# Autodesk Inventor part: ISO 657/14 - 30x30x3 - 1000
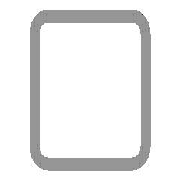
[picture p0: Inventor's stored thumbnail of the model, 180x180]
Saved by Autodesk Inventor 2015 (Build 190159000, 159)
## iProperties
Created: 2014-02
Part Number: ISO 657/14 - 30x30x3 - 1000
Material: Steel, Mild
Description: Hot-rolled steel sections - part 14: hot-finished structrual hollow sections - Dimensions and sectional properties
Document SubType Name: Modeling
Standard: ISO
Designer: 徐冠倫
Standard Revision: Third edition 2000-03-15
Standards Organization: ISO
Language: en-US
Size Designation: 30x30x3
Categories: <MemberInstance><Categories><Category DisplayName="Structural Shapes" InternalName="089c4875-fa83-4c05-b084-43b9cc11f5ed" Mnemonic="GRDR"><CategoryParameter Dis
Stock Number: 30x30x3
Mass: 2422.11 g
Surface Area: 2063.16 cm^2
Volume: 308.549 cm^3
Density: 7.85 g/cm^3
Appearance: Semi-Polished
IsCustomPart: 1
_CCFamilyMember: 8
_CCFamilyDisplayName: ISO 657/14 - 2000 (Square) - Hot-rolled steel sections - part 14: hot-finished structrual hollow sections - Dimensions and sectional properties
_FrameMemberDoc: Frame Member File
_Version: 15.0.0
_GetPNFromCC: 1
Author: 徐冠倫
G_L: 1000.000 mm
G_W: 30.000 mm
G_H: 30.000 mm
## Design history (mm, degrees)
node "Start plane"
node "End plane"
sketch "Sketch"
  geometry: L1 (-15, -10.5)-(-15, 10.5); L2 (-10.5, 15)-(10.5, 15); L3 (15, 10.5)-(15, -10.5); L4 (10.5, -15)-(-10.5, -15); L5 (-10.5, 12)-(10.5, 12); L6 (12, 10.5)-(12, -10.5); L7 (10.5, -12)-(-10.5, -12); L8 (-12, -10.5)-(-12, 10.5); L9 (0, 22.305)-(0, -22.305) reference; L10 (-22.305, 0)-(22.305, 0) reference; A1 r 4.5 centre (-10.5, -10.5) between (-15, -10.5) and (-10.5, -15); A2 r 4.5 centre (-10.5, 10.5) between (-10.5, 15) and (-15, 10.5); A3 r 4.5 centre (10.5, 10.5) between (15, 10.5) and (10.5, 15); A4 r 4.5 centre (10.5, -10.5) between (10.5, -15) and (15, -10.5); A5 r 1.5 centre (-10.5, 10.5) between (-10.5, 12) and (-12, 10.5); A6 r 1.5 centre (10.5, 10.5) between (12, 10.5) and (10.5, 12); A7 r 1.5 centre (10.5, -10.5) between (10.5, -12) and (12, -10.5); A8 r 1.5 centre (-10.5, -10.5) between (-12, -10.5) and (-10.5, -12)
  constraints: 16 end point, 16 point on circle, 8 centre point, 8 tangent, 4 parallel, 3 equal radius, 2 perpendicular, 7 other
  dimensions: "d7" = 4.5 radius of A1 (= G_IR); "d10" = 30 distance between parallel lines of L2 L4 (= G_H); "d11" = 30 distance between parallel lines of L1 L3 (= G_W); "d12" = 3 distance between parallel lines of L3 L6 (= G_T); "d15" = 15 distance between parallel lines of L2 L10 (= 0.5 x d10); "d16" = 15 distance between parallel lines of L9 L3 (= 0.5 x d11)
extrude "Body" new body sketch "Sketch" stored distance "d3" = 1000 (= G_L); taper "d4" = 0 deg
node "Driven Length"
  sketch "Sketch3"
    geometry: L1 (0, 0)-(10, 0) reference
    constraints: 2 end point, 1 horizontal
  workplane "Work Plane3"
  sketch "Sketch4"
    geometry: L1 (-2, 0)-(12, 0) reference; L2 (-2, 1000)-(12, 1000) reference
    dimensions: "d18" = 1000 distance between parallel lines of L1 L2 (derived)
body "Solid1"
other parameters: "G_W" = 30 [user parameter; used in 1 equation term], "G_H" = 30 [user parameter; used in 1 equation term], "G_T" = 3 [user parameter; used in 1 equation term], "G_IR" = 4.5 [user parameter; used in 1 equation term], "G_L" = 1000 (= d18) [user parameter; used in 1 equation term], "G_OFFSET_START" = 0 [user parameter; used in 1 equation term], "G_OFFSET_END" = 0 [user parameter; used in 1 equation term], "d13" = 0 (computed from G_OFFSET_START), "d17" = 90 deg
